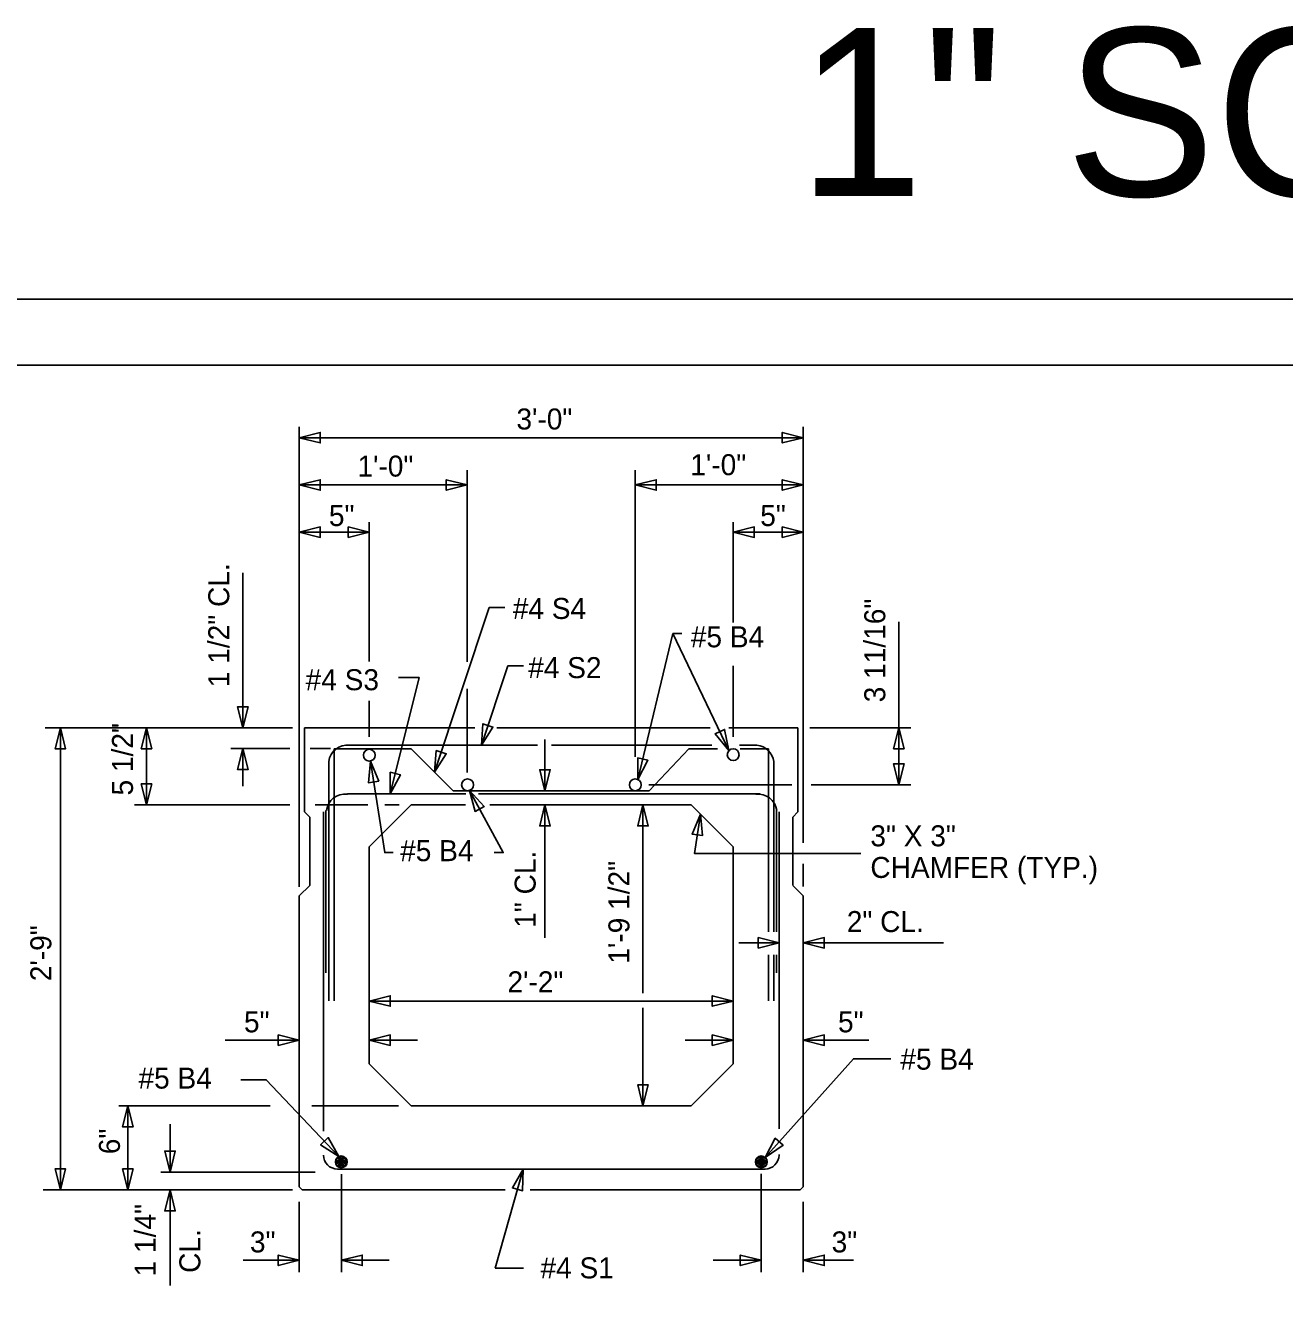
# Model space of a CAD drawing. Extents: x -38 to 94, y -165 to 80.
# Drawn here: x -26.07 to -18.57, y -148.98 to -141.37 of the extents above; entities that cross this region are included whole.
import ezdxf

# ---------------------------------------------------------------- set-up
doc = ezdxf.new("R2010")
doc.units = 0
for name, color, linetype in [('Arrowhead Terminators CELL', 7, 'Continuous'), ('Box Beam', 7, 'Continuous'), ('Dimension Lines', 7, 'Continuous'), ('Plan Sheet CELL', 7, 'Continuous'), ('Plot Shape CELL', 7, 'Continuous'), ('Rebar Lines', 7, 'Continuous'), ('Text', 7, 'Continuous'), ('User Information Notes', 7, 'Continuous')]:
    doc.layers.add(name, color=color, linetype=linetype)

msp = doc.modelspace()

# ---------------------------------------------------------------- linework, layer by layer
at = {"layer": 'Arrowhead Terminators CELL'}
for points in [[(-24.4385, -143.8251), (-24.3135, -143.8564), (-24.3135, -143.7939)], [(-21.4382, -143.8251), (-21.5632, -143.7939), (-21.5632, -143.8564)], [(-24.4385, -144.1062), (-24.3135, -144.1375), (-24.3135, -144.075)], [(-23.4387, -144.1062), (-23.5637, -144.075), (-23.5637, -144.1375)], [(-22.438, -144.1062), (-22.313, -144.1375), (-22.313, -144.075)], [(-21.4382, -144.1062), (-21.5632, -144.075), (-21.5632, -144.1375)], [(-24.4385, -144.3873), (-24.3135, -144.4185), (-24.3135, -144.356)], [(-24.0218, -144.3873), (-24.1468, -144.356), (-24.1468, -144.4185)], [(-21.8548, -144.3873), (-21.7298, -144.4185), (-21.7298, -144.356)], [(-21.4382, -144.3873), (-21.5632, -144.356), (-21.5632, -144.4185)], [(-24.7752, -145.5519), (-24.7439, -145.4269), (-24.8064, -145.4269)], [(-23.3545, -145.6558), (-23.2856, -145.547), (-23.3449, -145.5274)], [(-25.8614, -145.5519), (-25.8927, -145.6769), (-25.8302, -145.6769)], [(-25.3486, -145.5519), (-25.3798, -145.6769), (-25.3173, -145.6769)], [(-21.8802, -145.6877), (-21.9061, -145.5615), (-21.9624, -145.5885)], [(-20.8689, -145.5519), (-20.9001, -145.6769), (-20.8376, -145.6769)], [(-24.7752, -145.675), (-24.8064, -145.8), (-24.7439, -145.8)], [(-24.0156, -145.75), (-24.0271, -145.8783), (-23.9654, -145.8687)], [(-23.6326, -145.8155), (-23.5636, -145.7066), (-23.623, -145.687)], [(-22.4223, -145.8595), (-22.3629, -145.7452), (-22.4236, -145.7306)], [(-23.8968, -145.9452), (-23.8363, -145.8314), (-23.897, -145.8163)], [(-22.9758, -145.9263), (-22.9445, -145.8013), (-23.007, -145.8013)], [(-20.8689, -145.8911), (-20.8376, -145.7661), (-20.9001, -145.7661)], [(-25.3486, -146.0103), (-25.3173, -145.8853), (-25.3798, -145.8853)], [(-23.4243, -145.9241), (-23.3923, -146.0489), (-23.3374, -146.0192)], [(-22.9758, -146.0103), (-23.007, -146.1353), (-22.9445, -146.1353)], [(-22.3924, -146.0103), (-22.4237, -146.1353), (-22.3612, -146.1353)], [(-22.0501, -146.0651), (-22.1, -146.1839), (-22.0382, -146.1934)], [(-21.5812, -146.8313), (-21.7062, -146.8001), (-21.7062, -146.8626)], [(-21.4382, -146.8313), (-21.3132, -146.8626), (-21.3132, -146.8001)], [(-24.0218, -147.1781), (-23.8968, -147.2094), (-23.8968, -147.1469)], [(-21.8549, -147.1781), (-21.9799, -147.1469), (-21.9799, -147.2094)], [(-24.4385, -147.411), (-24.5635, -147.3798), (-24.5635, -147.4423)], [(-24.0218, -147.411), (-23.8968, -147.4423), (-23.8968, -147.3798)], [(-21.8549, -147.411), (-21.9799, -147.3798), (-21.9799, -147.4423)], [(-21.4382, -147.411), (-21.3132, -147.4423), (-21.3132, -147.3798)], [(-22.3924, -147.8018), (-22.3612, -147.6768), (-22.4237, -147.6768)], [(-25.4594, -147.8018), (-25.4907, -147.9268), (-25.4282, -147.9268)], [(-24.2029, -148.103), (-24.2662, -147.9907), (-24.3116, -148.0337)], [(-21.6648, -148.1087), (-21.5582, -148.0363), (-21.6048, -147.9946)], [(-25.2084, -148.1965), (-25.1772, -148.0715), (-25.2397, -148.0715)], [(-25.8614, -148.3019), (-25.8302, -148.1769), (-25.8927, -148.1769)], [(-25.4594, -148.3019), (-25.4282, -148.1769), (-25.4907, -148.1769)], [(-23.1053, -148.1783), (-23.1693, -148.2901), (-23.1092, -148.3071)], [(-25.2084, -148.3019), (-25.2397, -148.4269), (-25.1772, -148.4269)], [(-24.4385, -148.721), (-24.5635, -148.6898), (-24.5635, -148.7523)], [(-24.1887, -148.721), (-24.0637, -148.7523), (-24.0637, -148.6898)], [(-21.688, -148.721), (-21.813, -148.6898), (-21.813, -148.7523)], [(-21.4382, -148.721), (-21.3132, -148.7523), (-21.3132, -148.6898)]]:
    msp.add_lwpolyline(points, close=True, dxfattribs=at)
at = {"layer": 'Box Beam'}
for p, q in [((-24.4072, -146.0519), (-24.4072, -145.5519)), ((-24.4072, -145.5519), (-23.394, -145.5519)), ((-23.2622, -145.5519), (-21.9913, -145.5519)), ((-21.8815, -145.5519), (-21.4694, -145.5519)), ((-21.4694, -145.5519), (-21.4694, -146.0519)), ((-24.3759, -146.0832), (-24.4072, -146.0519)), ((-24.0218, -146.2603), (-23.7717, -146.0103)), ((-23.7717, -146.0103), (-23.4495, -146.0103)), ((-23.3048, -146.0103), (-22.1049, -146.0103)), ((-22.1049, -146.0103), (-21.8549, -146.2603)), ((-21.4694, -146.0519), (-21.5007, -146.0832)), ((-24.3759, -146.4895), (-24.3759, -146.0832)), ((-21.5003, -146.0828), (-21.5003, -146.4891)), ((-24.0218, -146.2603), (-24.0218, -147.5518)), ((-21.8549, -146.2603), (-21.8549, -147.5518)), ((-24.4385, -146.552), (-24.3759, -146.4895)), ((-21.5007, -146.4895), (-21.4382, -146.552)), ((-24.4385, -148.2841), (-24.4385, -146.552)), ((-21.4382, -146.552), (-21.4382, -148.2841)), ((-23.7717, -147.8018), (-24.0218, -147.5518)), ((-21.8549, -147.5518), (-22.1049, -147.8018)), ((-22.1049, -147.8018), (-23.7717, -147.8018)), ((-24.4385, -148.2841), (-24.4206, -148.3019)), ((-23.2121, -148.3019), (-24.4206, -148.3019)), ((-21.456, -148.3019), (-23.0631, -148.3019)), ((-21.4381, -148.284), (-21.456, -148.3019))]:
    msp.add_line(p, q, dxfattribs=at)
at = {"layer": 'Dimension Lines'}
for p, q in [((-24.4385, -146.4992), (-24.4385, -143.76)), ((-21.4382, -146.2361), (-21.4382, -143.76)), ((-24.4385, -143.8251), (-21.4382, -143.8251)), ((-23.4387, -145.159), (-23.4387, -144.0184)), ((-22.438, -145.7251), (-22.438, -144.0184)), ((-24.4385, -144.1062), (-23.4387, -144.1062)), ((-22.438, -144.1062), (-21.4382, -144.1062)), ((-24.0218, -144.3873), (-24.4385, -144.3873)), ((-24.0218, -145.1568), (-24.0218, -144.3285)), ((-21.8548, -144.9256), (-21.8548, -144.3285)), ((-21.8548, -144.3873), (-21.4382, -144.3873)), ((-24.7752, -144.6292), (-24.7752, -145.5519)), ((-23.6326, -145.8155), (-23.3083, -144.8359)), ((-23.3083, -144.8359), (-23.2138, -144.8359)), ((-20.8689, -144.9208), (-20.8689, -145.5519)), ((-22.2143, -144.9903), (-22.4223, -145.8595)), ((-22.161, -144.9903), (-22.2143, -144.9903)), ((-22.2143, -144.9903), (-21.8802, -145.6877)), ((-23.3545, -145.6558), (-23.1978, -145.1825)), ((-23.1978, -145.1825), (-23.1033, -145.1825)), ((-21.8548, -145.605), (-21.8548, -145.1829)), ((-23.4387, -145.8179), (-23.4387, -145.3206)), ((-24.0218, -145.605), (-24.0218, -145.3919)), ((-24.4787, -145.5519), (-25.9524, -145.5519)), ((-25.8614, -148.3019), (-25.8614, -145.5519)), ((-25.3486, -145.5519), (-25.3486, -146.0103)), ((-21.3979, -145.5519), (-20.7974, -145.5519)), ((-20.8689, -145.8911), (-20.8689, -145.5519)), ((-24.4954, -145.675), (-24.8467, -145.675)), ((-24.7752, -145.675), (-24.7752, -145.8985)), ((-24.2521, -145.675), (-24.373, -145.675)), ((-22.9758, -145.9263), (-22.9758, -145.6208)), ((-22.3575, -145.8911), (-21.5057, -145.8911)), ((-21.3913, -145.8911), (-20.7974, -145.8911)), ((-24.4954, -146.0103), (-25.4201, -146.0103)), ((-24.03, -146.0103), (-24.3445, -146.0103)), ((-23.8432, -146.0103), (-23.9297, -146.0103)), ((-22.9758, -146.802), (-22.9758, -146.0103)), ((-22.3924, -147.132), (-22.3924, -146.0103)), ((-21.4382, -146.496), (-21.4382, -146.3621)), ((-21.8222, -146.8313), (-21.5812, -146.8313)), ((-20.6017, -146.8313), (-21.4382, -146.8313)), ((-24.0218, -147.1781), (-21.8549, -147.1781)), ((-22.3924, -147.8018), (-22.3924, -147.2194)), ((-24.8801, -147.411), (-24.4385, -147.411)), ((-23.7357, -147.411), (-24.0218, -147.411)), ((-22.1409, -147.411), (-21.8549, -147.411)), ((-21.0471, -147.411), (-21.4382, -147.411)), ((-24.6131, -147.8018), (-25.5129, -147.8018)), ((-25.4594, -148.3019), (-25.4594, -147.8018)), ((-23.8485, -147.8018), (-24.3631, -147.8018)), ((-25.2084, -147.9104), (-25.2084, -148.1965)), ((-23.1053, -148.1783), (-23.2718, -148.7683)), ((-24.3434, -148.1965), (-25.2633, -148.1965)), ((-24.1878, -148.2088), (-24.1878, -148.7926)), ((-21.688, -148.2067), (-21.688, -148.7926)), ((-24.4787, -148.3019), (-25.9642, -148.3019)), ((-25.2084, -148.8711), (-25.2084, -148.3019)), ((-24.4385, -148.3734), (-24.4385, -148.7926)), ((-21.4382, -148.3734), (-21.4382, -148.7926)), ((-24.7723, -148.721), (-24.4385, -148.721)), ((-23.9026, -148.721), (-24.1887, -148.721)), ((-21.974, -148.721), (-21.688, -148.721)), ((-21.1378, -148.721), (-21.4382, -148.721)), ((-23.2718, -148.7683), (-23.1031, -148.7683))]:
    msp.add_line(p, q, dxfattribs=at)
for points in [[(-23.8968, -145.9452), (-23.725, -145.2531), (-23.8474, -145.2531)], [(-24.0156, -145.75), (-23.9303, -146.2941), (-23.8805, -146.2941)], [(-23.4243, -145.9241), (-23.2244, -146.2941), (-23.2786, -146.2941)], [(-22.0501, -146.0651), (-22.0861, -146.2996), (-21.0944, -146.2996)], [(-21.6648, -148.1087), (-21.1393, -147.521), (-20.9165, -147.521)], [(-24.2029, -148.103), (-24.6354, -147.6465), (-24.787, -147.6465)]]:
    msp.add_lwpolyline(points, dxfattribs=at)
at = {"layer": 'Plan Sheet CELL'}
msp.add_line((-32.4443, -143.3938), (-0.4439, -143.3938), dxfattribs=at)
at = {"layer": 'Plot Shape CELL'}
msp.add_lwpolyline([(-33.4983, -142.9999), (-0.4352, -142.9999), (-0.4352, -164.9999), (-33.4983, -164.9999)], close=True, dxfattribs=at)
at = {"layer": 'Rebar Lines'}
for p, q in [((-24.232, -145.6763), (-23.7718, -145.6763)), ((-24.232, -147.1763), (-24.232, -145.6763)), ((-24.1391, -145.6558), (-23.0193, -145.6558)), ((-23.7718, -145.6763), (-23.5217, -145.9263)), ((-22.937, -145.6558), (-21.9813, -145.6558)), ((-22.1182, -145.6763), (-22.355, -145.9263)), ((-22.1182, -145.6763), (-21.9478, -145.6763)), ((-21.8174, -145.6558), (-21.7143, -145.6558)), ((-21.814, -145.6763), (-21.6446, -145.6763)), ((-21.6446, -146.7656), (-21.6446, -145.6763)), ((-24.2633, -147.1763), (-24.2633, -145.7526)), ((-21.6133, -146.7656), (-21.6133, -145.7526)), ((-24.1514, -145.9452), (-23.4468, -145.9452)), ((-23.5217, -145.9263), (-22.355, -145.9263)), ((-23.3718, -145.9452), (-21.6944, -145.9452)), ((-24.2946, -146.0519), (-24.2946, -147.9529)), ((-24.2799, -147.0103), (-24.2799, -146.0431)), ((-21.5971, -146.7656), (-21.5971, -146.0398)), ((-21.582, -146.0519), (-21.582, -147.9392)), ((-21.6446, -147.1763), (-21.6446, -146.902)), ((-21.6133, -147.1763), (-21.6133, -146.902)), ((-21.5971, -147.0103), (-21.5971, -146.902)), ((-21.582, -148.0905), (-21.582, -148.0948)), ((-24.2112, -148.1783), (-21.6654, -148.1783))]:
    msp.add_line(p, q, dxfattribs=at)
for points in [[(-24.1904, -148.1018), (-24.1777, -148.1043), (-24.167, -148.1115), (-24.1598, -148.1222), (-24.1573, -148.1349), (-24.1598, -148.1476), (-24.167, -148.1583), (-24.1777, -148.1654), (-24.1904, -148.168), (-24.2031, -148.1654), (-24.2138, -148.1583), (-24.2209, -148.1476), (-24.2235, -148.1349), (-24.2209, -148.1222), (-24.2138, -148.1115), (-24.2031, -148.1043), (-24.1904, -148.1018), (-24.1904, -148.1349), (-24.1904, -148.168), (-24.1777, -148.1654), (-24.1904, -148.1349), (-24.167, -148.1583), (-24.1598, -148.1476), (-24.1904, -148.1349), (-24.1573, -148.1349), (-24.1598, -148.1222), (-24.1904, -148.1349), (-24.167, -148.1115), (-24.1777, -148.1043), (-24.1904, -148.1349), (-24.2031, -148.1043), (-24.2138, -148.1115), (-24.1904, -148.1349), (-24.2209, -148.1222), (-24.2235, -148.1349), (-24.1904, -148.1349), (-24.2209, -148.1476), (-24.2138, -148.1583), (-24.1904, -148.1349), (-24.2031, -148.1654)], [(-21.6862, -148.1018), (-21.6736, -148.1043), (-21.6629, -148.1115), (-21.6557, -148.1222), (-21.6532, -148.1349), (-21.6557, -148.1476), (-21.6629, -148.1583), (-21.6736, -148.1654), (-21.6862, -148.168), (-21.6989, -148.1654), (-21.7097, -148.1583), (-21.7168, -148.1476), (-21.7194, -148.1349), (-21.7168, -148.1222), (-21.7097, -148.1115), (-21.699, -148.1043), (-21.6862, -148.1018), (-21.6862, -148.1349), (-21.6862, -148.168), (-21.6736, -148.1654), (-21.6862, -148.1349), (-21.6629, -148.1583), (-21.6557, -148.1476), (-21.6862, -148.1349), (-21.6532, -148.1349), (-21.6557, -148.1222), (-21.6862, -148.1349), (-21.6629, -148.1115), (-21.6736, -148.1043), (-21.6862, -148.1349), (-21.699, -148.1043), (-21.7097, -148.1115), (-21.6862, -148.1349), (-21.7168, -148.1222), (-21.7194, -148.1349), (-21.6862, -148.1349), (-21.7168, -148.1476), (-21.7097, -148.1583), (-21.6862, -148.1349), (-21.6989, -148.1654)]]:
    msp.add_lwpolyline(points, dxfattribs=at)
for centre in [(-24.0218, -145.7148), (-21.8548, -145.7121), (-23.4367, -145.8911), (-22.4379, -145.8911), (-24.1887, -148.1352)]:
    msp.add_circle(centre, 0.0352, dxfattribs=at)
for centre, radius, start, end in [((-24.1528, -145.7664), 0.1114, 82.91815, 172.91815), ((-21.7242, -145.7667), 0.1118, 7.25072, 84.89839), ((-24.166, -146.0572), 0.1114, 82.91815, 172.91815), ((-21.7066, -146.0575), 0.1118, 7.25072, 97.25072), ((-24.2112, -148.0948), 0.0834, 180, 270), ((-21.6654, -148.0948), 0.0834, 270, 360)]:
    msp.add_arc(centre, radius, start, end, dxfattribs=at)
at = {"layer": 'User Information Notes'}
for p, q in [((-24.4385, -148.3019), (-24.4385, -148.3019)), ((-21.4382, -148.3019), (-21.4382, -148.3019))]:
    msp.add_line(p, q, dxfattribs=at)
msp.add_circle((-21.6879, -148.1352), 0.0352, dxfattribs=at)

# ---------------------------------------------------------------- texts
at = {"layer": 'Text'}
for s, p in [('3\'-0"', (-23.1457, -143.7762)), ('1\'-0"', (-24.0922, -144.0566)), ('1\'-0"', (-22.1102, -144.0482)), ('5"', (-24.2624, -144.3509)), ('#4 S4', (-23.1675, -144.9039)), ('#5 B4', (-22.1073, -145.0727)), ('#4 S2', (-23.0756, -145.2561)), ('#4 S3', (-24.4008, -145.3281)), ('3" X 3"', (-21.0381, -146.2572)), ('#5 B4', (-23.8381, -146.3455)), ('CHAMFER (TYP.)', (-21.0381, -146.4452)), ('2" CL.', (-21.1785, -146.7676)), ('2\'-2"', (-23.199, -147.126)), ('5"', (-24.7681, -147.3642)), ('5"', (-21.2309, -147.3642)), ('#5 B4', (-20.8595, -147.5864)), ('#5 B4', (-25.3963, -147.6991)), ('3"', (-24.7326, -148.6742)), ('3"', (-21.2688, -148.6742)), ('#4 S1', (-23.0025, -148.8287))]:
    msp.add_text(s, height=0.125, dxfattribs=at).set_placement(p)
for s, rotation, p in [('5"', 360, (-21.6939, -144.3509)), ('1 1/2" CL.', 90, (-24.8557, -145.3101)), ('3 11/16"', 90, (-20.9494, -145.4001)), ('5 1/2"', 90, (-25.4291, -145.9545)), ('1" CL.', 90, (-23.0313, -146.742)), ('1\'-9 1/2"', 90, (-22.4729, -146.9555)), ('2\'-9"', 90, (-25.9151, -147.0599)), ('6"', 90, (-25.5067, -148.0896)), ('1 1/4"', 90, (-25.2934, -148.817)), ('CL.', 90, (-25.0279, -148.7962))]:
    msp.add_text(s, height=0.125, rotation=rotation, dxfattribs=at).set_placement(p)
at = {"layer": 'User Information Notes'}
msp.add_text('1" SCALE', height=1, dxfattribs=at).set_placement((-21.467, -142.3871))

doc.saveas('drawing.dxf')
